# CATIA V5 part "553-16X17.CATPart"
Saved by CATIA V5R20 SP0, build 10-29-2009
Part number: 553-16X17
Definition: NONE
Nomenclature: 553-16X17
Source: Unknown
Description: 553-16X17
Bounding box of the stored display mesh (mm): x 0 to 17, y -13 to 13, z -13 to 13
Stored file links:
  C:\Users\Utente\Desktop\IO LAVORO\3D X SITO CF\X SITO\PLASTICA\553\553-16X17.CATPart
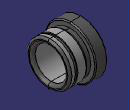
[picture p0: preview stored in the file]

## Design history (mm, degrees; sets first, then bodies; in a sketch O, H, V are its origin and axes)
Body1 "553-16X17" (main body)
  Solid1: solid without history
